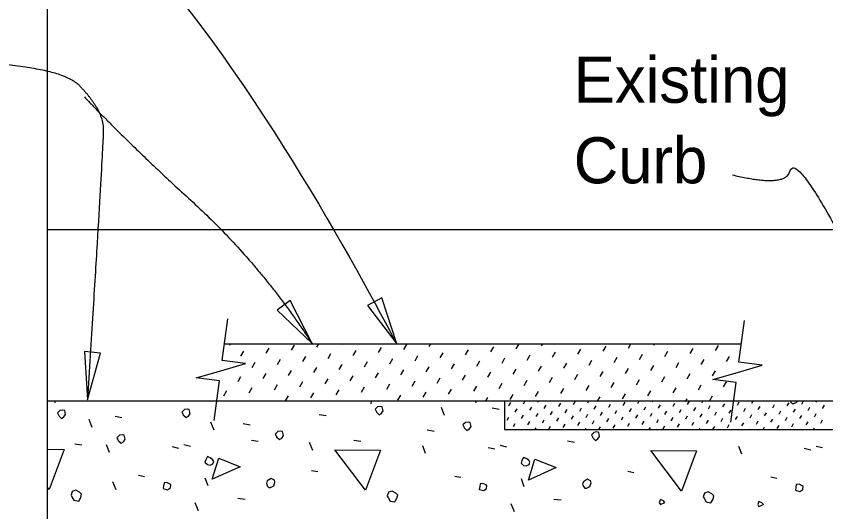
# Model space of a CAD drawing. Extents: x 1.5 to 68.7, y 0 to 31.
# Drawn here: x 25.337 to 28.879, y 11.448 to 13.614 of the extents above; entities that cross this region are included whole.
import ezdxf

# ---------------------------------------------------------------- set-up
doc = ezdxf.new("R2010")
doc.units = 0
for name, color, linetype in [('Dimension', 7, 'Continuous'), ('Miscellaneous', 7, 'Continuous'), ('TrafBarrierConc', 7, 'Continuous')]:
    doc.layers.add(name, color=color, linetype=linetype)

msp = doc.modelspace()

# ---------------------------------------------------------------- linework, layer by layer
at = {"layer": 'Dimension'}
for points in [[(26.6316, 12.1828), (26.5349, 12.3706), (26.4784, 12.3283)], [(27.0016, 12.1811), (26.9365, 12.3821), (26.8739, 12.3494)], [(25.6483, 11.937), (25.7052, 12.1404), (25.635, 12.1478)]]:
    msp.add_lwpolyline(points, close=True, dxfattribs=at)
for points in [[(26.2031, 11.8459), (26.2263, 12.0198), (26.1238, 12.0334), (26.2322, 12.0644), (26.3406, 12.0953), (26.2382, 12.109), (26.2625, 12.2913)], [(28.4639, 11.8386), (28.4871, 12.0124), (28.3846, 12.0261), (28.493, 12.057), (28.6014, 12.0879), (28.499, 12.1016), (28.5233, 12.284)]]:
    msp.add_lwpolyline(points, dxfattribs=at)
for points, degree in [([(24.5331, 14.4952), (24.8538, 14.4726), (25.7837, 14.4447), (26.8575, 12.4571), (27.0016, 12.1811)], 3), ([(24.8609, 13.4204), (25.5071, 13.4204), (25.7178, 13.2026), (25.7178, 13.041), (25.6483, 11.9369)], 2), ([(25.635, 13.2612), (25.8091, 13.0761), (26.4025, 12.5334), (26.6316, 12.1828)], 2), ([(28.4708, 12.9203), (28.7034, 12.864), (28.7449, 13.0099), (29.089, 12.3912), (29.2714, 12.2154)], 2)]:
    msp.add_open_spline(points, degree=degree, dxfattribs=at)
at = {"layer": 'Miscellaneous'}
for p, q in [((26.2715, 12.1764), (26.2747, 12.182)), ((26.431, 12.1405), (26.4439, 12.1629)), ((26.5416, 12.1535), (26.5546, 12.1759)), ((26.6522, 12.1665), (26.6612, 12.182)), ((26.7629, 12.1794), (26.7643, 12.182)), ((26.8117, 12.1306), (26.8247, 12.153)), ((26.9223, 12.1435), (26.9353, 12.1659)), ((27.033, 12.1565), (27.0459, 12.1789)), ((27.1436, 12.1695), (27.1508, 12.182)), ((27.3031, 12.1336), (27.316, 12.156)), ((27.4137, 12.1466), (27.4267, 12.169)), ((27.5243, 12.1595), (27.5373, 12.1819)), ((27.635, 12.1725), (27.6405, 12.182)), ((27.7944, 12.1366), (27.8074, 12.159)), ((27.9051, 12.1496), (27.918, 12.172)), ((28.0157, 12.1625), (28.0269, 12.182)), ((28.1263, 12.1755), (28.1301, 12.182)), ((28.2858, 12.1396), (28.2988, 12.162)), ((28.3964, 12.1526), (28.4094, 12.175)), ((26.3203, 12.1276), (26.3333, 12.15)), ((26.5904, 12.1047), (26.6034, 12.127)), ((26.7011, 12.1176), (26.714, 12.14)), ((26.9712, 12.0947), (26.9841, 12.1171)), ((27.0818, 12.1077), (27.0948, 12.1301)), ((27.1924, 12.1206), (27.2054, 12.143)), ((27.4625, 12.0977), (27.4755, 12.1201)), ((27.5732, 12.1107), (27.5861, 12.1331)), ((27.6838, 12.1237), (27.6968, 12.146)), ((27.9539, 12.1008), (27.9669, 12.1231)), ((28.0645, 12.1137), (28.0775, 12.1361)), ((28.1752, 12.1267), (28.1881, 12.1491)), ((28.4453, 12.1038), (28.4582, 12.1262)), ((26.3692, 12.0787), (26.3821, 12.1011)), ((26.4798, 12.0917), (26.4928, 12.1141)), ((26.7499, 12.0688), (26.7629, 12.0912)), ((26.8605, 12.0817), (26.8735, 12.1041)), ((27.1306, 12.0588), (27.1436, 12.0812)), ((27.2413, 12.0718), (27.2542, 12.0942)), ((27.3519, 12.0848), (27.3649, 12.1072)), ((27.622, 12.0619), (27.635, 12.0843)), ((27.7326, 12.0748), (27.7456, 12.0972)), ((27.8433, 12.0878), (27.8562, 12.1102)), ((28.1134, 12.0649), (28.1263, 12.0873)), ((28.224, 12.0778), (28.237, 12.1002)), ((28.3346, 12.0908), (28.3476, 12.1132)), ((26.418, 12.0299), (26.431, 12.0523)), ((26.5286, 12.0429), (26.5416, 12.0652)), ((26.6393, 12.0558), (26.6522, 12.0782)), ((26.9094, 12.0329), (26.9223, 12.0553)), ((27.02, 12.0459), (27.033, 12.0683)), ((27.4007, 12.0359), (27.4137, 12.0583)), ((27.5114, 12.0489), (27.5243, 12.0713)), ((27.7815, 12.026), (27.7944, 12.0484)), ((27.8921, 12.039), (27.9051, 12.0613)), ((28.0027, 12.0519), (28.0157, 12.0743)), ((28.2728, 12.029), (28.2858, 12.0514)), ((28.3835, 12.042), (28.3964, 12.0644)), ((26.3074, 12.0169), (26.3203, 12.0393)), ((26.5775, 11.994), (26.5904, 12.0164)), ((26.6881, 12.007), (26.7011, 12.0294)), ((26.7987, 12.0199), (26.8117, 12.0423)), ((27.0688, 11.997), (27.0818, 12.0194)), ((27.1795, 12.01), (27.1924, 12.0324)), ((27.2901, 12.023), (27.3031, 12.0454)), ((27.5602, 12.0001), (27.5732, 12.0225)), ((27.6708, 12.013), (27.6838, 12.0354)), ((27.9409, 11.9901), (27.9539, 12.0125)), ((28.0516, 12.0031), (28.0645, 12.0255)), ((28.1622, 12.016), (28.1752, 12.0384)), ((28.4323, 11.9931), (28.4453, 12.0155)), ((26.2456, 11.9551), (26.2585, 11.9775)), ((26.3562, 11.9681), (26.3692, 11.9905)), ((26.4668, 11.9811), (26.4798, 12.0034)), ((26.7369, 11.9582), (26.7499, 11.9805)), ((26.8476, 11.9711), (26.8605, 11.9935)), ((26.9582, 11.9841), (26.9712, 12.0065)), ((27.2283, 11.9612), (27.2413, 11.9836)), ((27.3389, 11.9741), (27.3519, 11.9965)), ((27.4496, 11.9871), (27.4625, 12.0095)), ((27.7197, 11.9642), (27.7326, 11.9866)), ((27.8303, 11.9772), (27.8433, 11.9995)), ((28.1004, 11.9542), (28.1134, 11.9766)), ((28.211, 11.9672), (28.224, 11.9896)), ((28.3217, 11.9802), (28.3346, 12.0026)), ((26.5157, 11.9322), (26.5286, 11.9546)), ((26.6263, 11.9452), (26.6393, 11.9676)), ((27.007, 11.9352), (27.02, 11.9576)), ((27.1177, 11.9482), (27.1306, 11.9706)), ((27.39, 11.9291), (27.4007, 11.9477)), ((27.4984, 11.9383), (27.5114, 11.9607)), ((27.609, 11.9512), (27.622, 11.9736)), ((27.8796, 11.9291), (27.8921, 11.9507)), ((27.9898, 11.9413), (28.0027, 11.9637)), ((28.2661, 11.9291), (28.2728, 11.9408)), ((28.3705, 11.9313), (28.3835, 11.9537)), ((27.4931, 11.9111), (27.5012, 11.9251)), ((27.5566, 11.9192), (27.564, 11.932)), ((27.5843, 11.8915), (27.5924, 11.9055)), ((27.6201, 11.9273), (27.6228, 11.932)), ((27.6477, 11.8996), (27.6558, 11.9136)), ((27.7112, 11.9077), (27.7193, 11.9217)), ((27.7747, 11.9158), (27.7828, 11.9298)), ((27.8382, 11.9239), (27.8429, 11.932)), ((27.8659, 11.8962), (27.874, 11.9102)), ((27.9294, 11.9043), (27.9375, 11.9183)), ((27.9929, 11.9124), (28.001, 11.9264)), ((28.0564, 11.9205), (28.063, 11.932)), ((28.0841, 11.8928), (28.0922, 11.9068)), ((28.1199, 11.9286), (28.1218, 11.932)), ((28.1476, 11.9009), (28.1557, 11.9149)), ((28.2111, 11.909), (28.2192, 11.923)), ((28.2746, 11.9171), (28.2827, 11.9311)), ((28.3381, 11.9252), (28.342, 11.932)), ((28.3658, 11.8976), (28.3739, 11.9115)), ((28.4292, 11.9057), (28.4373, 11.9196)), ((28.4671, 11.9285), (28.4658, 11.932)), ((28.4927, 11.9138), (28.5008, 11.9278)), ((28.5562, 11.9219), (28.5621, 11.932)), ((28.5839, 11.8942), (28.592, 11.9082)), ((28.6197, 11.93), (28.6209, 11.932)), ((28.6474, 11.9023), (28.6555, 11.9163)), ((28.7109, 11.9104), (28.719, 11.9244)), ((28.7744, 11.9185), (28.7822, 11.932)), ((28.8021, 11.8908), (28.8102, 11.9048)), ((28.8379, 11.9266), (28.841, 11.932)), ((28.8656, 11.8989), (28.8737, 11.9129)), ((26.6626, 11.8732), (26.6926, 11.8679)), ((27.2115, 11.8681), (27.1974, 11.9034)), ((27.4195, 11.9013), (27.4495, 11.896)), ((27.5208, 11.8834), (27.5289, 11.8974)), ((27.5485, 11.8557), (27.5566, 11.8697)), ((27.6119, 11.8638), (27.6201, 11.8778)), ((27.6754, 11.8719), (27.6835, 11.8859)), ((27.7389, 11.88), (27.747, 11.894)), ((27.8024, 11.8881), (27.8105, 11.9021)), ((27.8301, 11.8604), (27.8382, 11.8744)), ((27.8936, 11.8685), (27.9017, 11.8825)), ((27.9571, 11.8766), (27.9652, 11.8906)), ((28.0206, 11.8847), (28.0287, 11.8987)), ((28.0483, 11.857), (28.0564, 11.871)), ((28.1118, 11.8651), (28.1199, 11.8791)), ((28.1753, 11.8732), (28.1834, 11.8872)), ((28.2388, 11.8813), (28.2469, 11.8953)), ((28.3023, 11.8894), (28.3104, 11.9034)), ((28.33, 11.8618), (28.3381, 11.8757)), ((28.3934, 11.8699), (28.4016, 11.8839)), ((28.4569, 11.878), (28.465, 11.892)), ((28.5204, 11.8861), (28.5285, 11.9001)), ((28.5481, 11.8584), (28.5562, 11.8724)), ((28.6116, 11.8665), (28.6197, 11.8805)), ((28.6751, 11.8746), (28.6832, 11.8886)), ((28.7386, 11.8827), (28.7467, 11.8967)), ((28.7663, 11.855), (28.7744, 11.869)), ((28.8298, 11.8631), (28.8379, 11.8771)), ((25.6696, 11.816), (25.6555, 11.8513)), ((25.7695, 11.8652), (25.7995, 11.8599)), ((26.2023, 11.8039), (26.1881, 11.8393)), ((26.3301, 11.8332), (26.3602, 11.8279)), ((27.485, 11.8476), (27.4931, 11.8616)), ((27.5127, 11.8199), (27.5208, 11.8339)), ((27.5762, 11.828), (27.5843, 11.842)), ((27.6396, 11.8361), (27.6477, 11.8501)), ((27.7031, 11.8442), (27.7112, 11.8582)), ((27.7666, 11.8523), (27.7747, 11.8663)), ((27.7943, 11.8246), (27.8024, 11.8386)), ((27.8578, 11.8327), (27.8659, 11.8467)), ((27.9213, 11.8408), (27.9294, 11.8548)), ((27.9848, 11.8489), (27.9929, 11.8629)), ((28.0125, 11.8212), (28.0206, 11.8352)), ((28.076, 11.8293), (28.0841, 11.8433)), ((28.1395, 11.8374), (28.1476, 11.8514)), ((28.203, 11.8456), (28.2111, 11.8595)), ((28.2665, 11.8537), (28.2746, 11.8676)), ((28.2942, 11.826), (28.3023, 11.84)), ((28.3577, 11.8341), (28.3658, 11.8481)), ((28.4211, 11.8422), (28.4292, 11.8562)), ((28.4846, 11.8503), (28.4927, 11.8643)), ((28.5123, 11.8226), (28.5204, 11.8366)), ((28.5758, 11.8307), (28.5839, 11.8447)), ((28.6393, 11.8388), (28.6474, 11.8528)), ((28.7028, 11.8469), (28.7109, 11.8609)), ((28.7305, 11.8192), (28.7386, 11.8332)), ((28.794, 11.8273), (28.8021, 11.8413)), ((28.8575, 11.8354), (28.8656, 11.8494)), ((27.1351, 11.8051), (27.1652, 11.7998)), ((27.6077, 11.807), (27.6119, 11.8143)), ((27.6673, 11.8084), (27.6754, 11.8224)), ((27.7308, 11.8165), (27.7389, 11.8305)), ((27.8278, 11.807), (27.8301, 11.8109)), ((27.8866, 11.807), (27.8936, 11.819)), ((27.949, 11.8131), (27.9571, 11.8271)), ((28.048, 11.807), (28.0483, 11.8075)), ((28.1068, 11.807), (28.1118, 11.8156)), ((28.1672, 11.8098), (28.1753, 11.8237)), ((28.2307, 11.8179), (28.2388, 11.8319)), ((28.3269, 11.807), (28.33, 11.8123)), ((28.3857, 11.807), (28.3934, 11.8204)), ((28.4488, 11.8145), (28.4569, 11.8285)), ((28.547, 11.807), (28.5481, 11.8089)), ((28.6058, 11.807), (28.6116, 11.817)), ((28.667, 11.8111), (28.6751, 11.8251)), ((28.826, 11.807), (28.8298, 11.8136)), ((25.5932, 11.745), (25.6233, 11.7397)), ((25.7448, 11.7062), (25.7324, 11.7398)), ((26.0188, 11.7327), (26.0471, 11.7257)), ((26.0705, 11.742), (26.0988, 11.7349)), ((26.3662, 11.761), (26.3962, 11.7557)), ((26.6348, 11.7158), (26.6206, 11.7511)), ((26.8147, 11.761), (26.8448, 11.7557)), ((27.1281, 11.7027), (27.1157, 11.7363)), ((27.4021, 11.7292), (27.4304, 11.7221)), ((27.4538, 11.7385), (27.4821, 11.7314)), ((27.7495, 11.7575), (27.7795, 11.7522)), ((28.5114, 11.6991), (28.499, 11.7327)), ((28.8371, 11.7349), (28.8654, 11.7279)), ((28.7854, 11.7257), (28.8137, 11.7186)), ((26.6296, 11.6284), (26.6561, 11.6231)), ((28.0129, 11.6249), (28.0394, 11.6196)), ((25.8721, 11.6072), (25.8986, 11.6019)), ((26.1766, 11.5608), (26.1642, 11.5944)), ((27.2554, 11.6037), (27.2819, 11.5984)), ((27.5599, 11.5573), (27.5475, 11.5909)), ((28.6387, 11.6002), (28.6652, 11.5948)), ((25.7737, 11.5434), (25.7596, 11.5788)), ((26.1342, 11.4512), (26.12, 11.4866)), ((26.3061, 11.5065), (26.3379, 11.5029)), ((27.5174, 11.4477), (27.5033, 11.483)), ((27.6894, 11.5029), (27.7212, 11.4994))]:
    msp.add_line(p, q, dxfattribs=at)
for points in [[(25.5073, 11.932), (25.5061, 11.9232)], [(26.8902, 11.932), (26.8885, 11.9197)], [(26.9141, 11.8816), (26.9247, 11.871), (26.9353, 11.8781), (26.9424, 11.8887), (26.9388, 11.9064), (26.93, 11.9081), (26.9176, 11.9064), (26.907, 11.8958), (26.9141, 11.8816)], [(27.3429, 11.932), (27.3499, 11.925)], [(28.724, 11.932), (28.7252, 11.9285), (28.7323, 11.9215)], [(28.7323, 11.9215), (28.7393, 11.9215), (28.7535, 11.9285), (28.7546, 11.932)], [(25.5244, 11.8656), (25.535, 11.855), (25.5456, 11.862), (25.5527, 11.8727), (25.5491, 11.8903), (25.5403, 11.8921), (25.5279, 11.8903), (25.5173, 11.8797), (25.5244, 11.8656)], [(26.0691, 11.8696), (26.0797, 11.859), (26.0903, 11.8661), (26.0973, 11.8767), (26.0938, 11.8943), (26.085, 11.8961), (26.0726, 11.8943), (26.062, 11.8837), (26.0691, 11.8696)], [(27.2986, 11.8135), (27.3092, 11.8029), (27.3198, 11.8099), (27.3269, 11.8205), (27.3233, 11.8382), (27.3145, 11.84), (27.3021, 11.8382), (27.2915, 11.8276), (27.2986, 11.8135)], [(26.4776, 11.7734), (26.4882, 11.7628), (26.4988, 11.7699), (26.5058, 11.7805), (26.5023, 11.7981), (26.4935, 11.7999), (26.4811, 11.7981), (26.4705, 11.7875), (26.4776, 11.7734)], [(25.7847, 11.7574), (25.7953, 11.7468), (25.8059, 11.7538), (25.813, 11.7644), (25.8095, 11.7821), (25.8006, 11.7839), (25.7882, 11.7821), (25.7776, 11.7715), (25.7847, 11.7574)], [(27.8608, 11.7699), (27.8714, 11.7593), (27.8821, 11.7663), (27.8891, 11.7769), (27.8856, 11.7946), (27.8767, 11.7964), (27.8644, 11.7946), (27.8538, 11.784), (27.8608, 11.7699)], [(25.4726, 11.721), (25.5468, 11.7204), (25.4814, 11.5454)], [(26.8647, 11.5418), (26.7304, 11.7186), (26.9301, 11.7168), (26.8647, 11.5418)], [(28.248, 11.5383), (28.1136, 11.7151), (28.3134, 11.7133), (28.248, 11.5383)], [(26.1731, 11.6536), (26.1854, 11.6519), (26.1978, 11.6572), (26.2013, 11.6678), (26.196, 11.6766), (26.1854, 11.6837), (26.1731, 11.689), (26.166, 11.6748), (26.1625, 11.6642), (26.1731, 11.6536)], [(26.1947, 11.5895), (26.223, 11.6815), (26.3167, 11.6443), (26.1947, 11.5895)], [(27.5563, 11.6501), (27.5687, 11.6483), (27.5811, 11.6536), (27.5846, 11.6642), (27.5793, 11.6731), (27.5687, 11.6801), (27.5563, 11.6854), (27.5493, 11.6713), (27.5457, 11.6607), (27.5563, 11.6501)], [(27.578, 11.586), (27.6063, 11.6779), (27.7, 11.6408), (27.578, 11.586)], [(26.4422, 11.5542), (26.4493, 11.5542), (26.4634, 11.5613), (26.4687, 11.5772), (26.467, 11.586), (26.4528, 11.5931), (26.4351, 11.5825), (26.4316, 11.5719), (26.4351, 11.5613), (26.4422, 11.5542)], [(27.8255, 11.5507), (27.8326, 11.5507), (27.8467, 11.5577), (27.852, 11.5736), (27.8502, 11.5825), (27.8361, 11.5895), (27.8184, 11.5789), (27.8149, 11.5683), (27.8184, 11.5577), (27.8255, 11.5507)], [(25.4814, 11.5454), (25.4726, 11.557)], [(25.9799, 11.5489), (25.9994, 11.5436), (26.0118, 11.5524), (26.0135, 11.5648), (26.01, 11.5683), (25.9958, 11.5754), (25.9835, 11.5736), (25.9817, 11.5613), (25.9799, 11.5489)], [(27.3632, 11.5454), (27.3827, 11.54), (27.395, 11.5489), (27.3968, 11.5613), (27.3933, 11.5648), (27.3791, 11.5719), (27.3667, 11.5701), (27.365, 11.5577), (27.3632, 11.5454)], [(28.7465, 11.5418), (28.7659, 11.5365), (28.7783, 11.5454), (28.7801, 11.5577), (28.7765, 11.5613), (28.7624, 11.5683), (28.75, 11.5666), (28.7483, 11.5542), (28.7465, 11.5418)], [(25.5804, 11.5135), (25.5893, 11.4976), (25.6105, 11.4941), (25.6193, 11.51), (25.6228, 11.5241), (25.614, 11.533), (25.5981, 11.5418), (25.5822, 11.5365), (25.5769, 11.5206), (25.5804, 11.5135)], [(26.9637, 11.51), (26.9725, 11.4941), (26.9937, 11.4906), (27.0026, 11.5065), (27.0061, 11.5206), (26.9973, 11.5294), (26.9814, 11.5383), (26.9655, 11.533), (26.9602, 11.5171), (26.9637, 11.51)], [(28.347, 11.5065), (28.3558, 11.4906), (28.377, 11.487), (28.3859, 11.5029), (28.3894, 11.5171), (28.3806, 11.5259), (28.3647, 11.5347), (28.3487, 11.5294), (28.3434, 11.5135), (28.347, 11.5065)], [(28.1561, 11.4795), (28.1756, 11.4883), (28.1685, 11.4954), (28.1561, 11.5007), (28.1508, 11.4883), (28.1561, 11.4795)], [(28.5868, 11.4712), (28.6063, 11.4801), (28.5992, 11.4872), (28.5868, 11.4925), (28.5815, 11.4801), (28.5868, 11.4712)]]:
    msp.add_lwpolyline(points, dxfattribs=at)
at = {"layer": 'TrafBarrierConc'}
for p, q in [((25.4726, 14.7653), (25.4726, 12.682)), ((25.4726, 12.682), (25.4726, 10.0773)), ((25.4726, 12.682), (34.6205, 12.682)), ((26.2479, 12.182), (28.5097, 12.182)), ((25.4726, 11.932), (31.1267, 11.932)), ((27.4727, 11.932), (27.4727, 11.807)), ((27.4727, 11.807), (31.0765, 11.807))]:
    msp.add_line(p, q, dxfattribs=at)

# ---------------------------------------------------------------- texts
at = {"layer": 'Dimension'}
for s, p in [('Existing ', (27.7764, 13.2353)), ('Curb', (27.7764, 12.8833))]:
    msp.add_text(s, height=0.2016, dxfattribs=at).set_placement(p)

doc.saveas('drawing.dxf')
